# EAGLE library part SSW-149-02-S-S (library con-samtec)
THROUGH-HOLE .025" SQ POST SOCKET Source: Samtec SSW.pdf
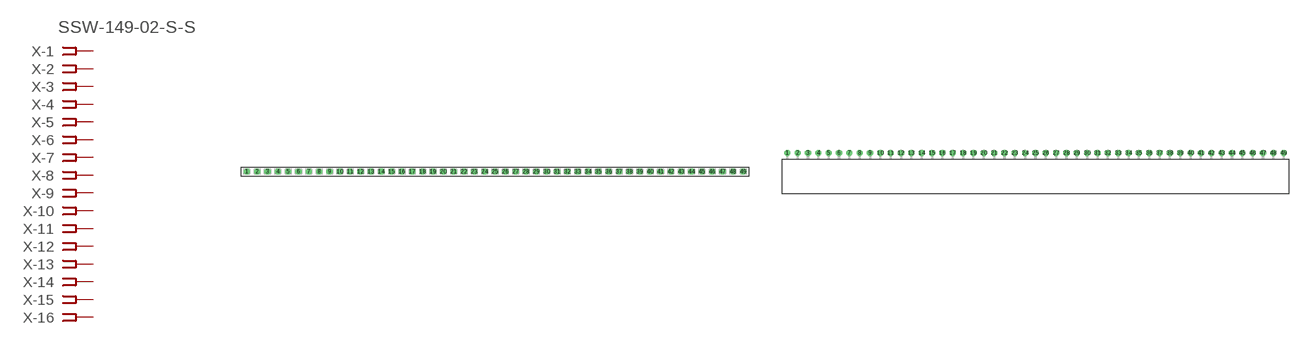
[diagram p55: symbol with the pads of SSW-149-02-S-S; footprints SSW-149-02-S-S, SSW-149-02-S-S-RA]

Designator prefix X; gates -1=FPINV -2=FPIN -3=FPIN -4=FPIN -5=FPIN -6=FPIN -7=FPIN -8=FPIN -9=FPIN -10=FPIN -11=FPIN -12=FPIN -13=FPIN -14=FPIN -15=FPIN -16=FPIN -17=FPIN -18=FPIN -19=FPIN -20=FPIN -21=FPIN -22=FPIN -23=FPIN -24=FPIN -25=FPIN -26=FPIN -27=FPIN -28=FPIN -29=FPIN -30=FPIN -31=FPIN -32=FPIN -33=FPIN -34=FPIN -35=FPIN -36=FPIN -37=FPIN -38=FPIN -39=FPIN -40=FPIN -41=FPIN -42=FPIN -43=FPIN -44=FPIN -45=FPIN -46=FPIN -47=FPIN -48=FPIN -49=FPIN

## SSW-149-02-S-S (OC_FARNELL: unknown; OC_NEWARK: unknown)  [SSW-149-02-S-S]
1  -1:1  pas
2  -2:1  pas
3  -3:1  pas
4  -4:1  pas
5  -5:1  pas
6  -6:1  pas
7  -7:1  pas
8  -8:1  pas
9  -9:1  pas
10  -10:1  pas
11  -11:1  pas
12  -12:1  pas
13  -13:1  pas
14  -14:1  pas
15  -15:1  pas
16  -16:1  pas
17  -17:1  pas
18  -18:1  pas
19  -19:1  pas
20  -20:1  pas
21  -21:1  pas
22  -22:1  pas
23  -23:1  pas
24  -24:1  pas
25  -25:1  pas
26  -26:1  pas
27  -27:1  pas
28  -28:1  pas
29  -29:1  pas
30  -30:1  pas
31  -31:1  pas
32  -32:1  pas
33  -33:1  pas
34  -34:1  pas
35  -35:1  pas
36  -36:1  pas
37  -37:1  pas
38  -38:1  pas
39  -39:1  pas
40  -40:1  pas
41  -41:1  pas
42  -42:1  pas
43  -43:1  pas
44  -44:1  pas
45  -45:1  pas
46  -46:1  pas
47  -47:1  pas
48  -48:1  pas
49  -49:1  pas

## SSW-149-02-S-S-RA (OC_FARNELL: unknown; OC_NEWARK: unknown)  [SSW-149-02-S-S-RA]
Pads as for SSW-149-02-S-S

## Footprint SSW-149-02-S-S (pad centres in mm)
THROUGH-HOLE .025" SQ POST SOCKET Source: Samtec SSW.pdf
drill 1 pad 1.5 octagon: 1 -60.96,0; 2 -58.42,0; 3 -55.88,0; 4 -53.34,0; 5 -50.8,0; 6 -48.26,0; 7 -45.72,0; 8 -43.18,0; 9 -40.64,0; 10 -38.1,0; 11 -35.56,0; 12 -33.02,0; 13 -30.48,0; 14 -27.94,0; 15 -25.4,0; 16 -22.86,0; 17 -20.32,0; 18 -17.78,0; 19 -15.24,0; 20 -12.7,0; 21 -10.16,0; 22 -7.62,0; 23 -5.08,0; 24 -2.54,0; 25 0,0; 26 2.54,0; 27 5.08,0; 28 7.62,0; 29 10.16,0; 30 12.7,0; 31 15.24,0; 32 17.78,0; 33 20.32,0; 34 22.86,0; 35 25.4,0; 36 27.94,0; 37 30.48,0; 38 33.02,0; 39 35.56,0; 40 38.1,0; 41 40.64,0; 42 43.18,0; 43 45.72,0; 44 48.26,0; 45 50.8,0; 46 53.34,0; 47 55.88,0; 48 58.42,0; 49 60.96,0

## Footprint SSW-149-02-S-S-RA (pad centres in mm)
THROUGH-HOLE .025" SQ POST SOCKET Source: Samtec SSW.pdf
drill 1 pad 1.5 octagon: 1 -60.96,1.524; 2 -58.42,1.524; 3 -55.88,1.524; 4 -53.34,1.524; 5 -50.8,1.524; 6 -48.26,1.524; 7 -45.72,1.524; 8 -43.18,1.524; 9 -40.64,1.524; 10 -38.1,1.524; 11 -35.56,1.524; 12 -33.02,1.524; 13 -30.48,1.524; 14 -27.94,1.524; 15 -25.4,1.524; 16 -22.86,1.524; 17 -20.32,1.524; 18 -17.78,1.524; 19 -15.24,1.524; 20 -12.7,1.524; 21 -10.16,1.524; 22 -7.62,1.524; 23 -5.08,1.524; 24 -2.54,1.524; 25 0,1.524; 26 2.54,1.524; 27 5.08,1.524; 28 7.62,1.524; 29 10.16,1.524; 30 12.7,1.524; 31 15.24,1.524; 32 17.78,1.524; 33 20.32,1.524; 34 22.86,1.524; 35 25.4,1.524; 36 27.94,1.524; 37 30.48,1.524; 38 33.02,1.524; 39 35.56,1.524; 40 38.1,1.524; 41 40.64,1.524; 42 43.18,1.524; 43 45.72,1.524; 44 48.26,1.524; 45 50.8,1.524; 46 53.34,1.524; 47 55.88,1.524; 48 58.42,1.524; 49 60.96,1.524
